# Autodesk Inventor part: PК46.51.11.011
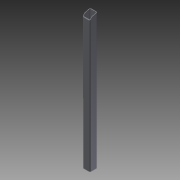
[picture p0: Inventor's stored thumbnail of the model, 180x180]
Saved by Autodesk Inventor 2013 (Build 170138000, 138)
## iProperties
Shininess: 64.0
Length Units: 11269
Angle Units: 11279
Time Units: 11290
Mass Units: 11283
Length Display Precision: 3
Angle Display Precision: 2
Compacted: True
Part Number: PК46.51.11.011
Document SubType Name: Modeling
Created: 2004-07
Material: Steel, Mild
Designer: =<Author>
Manufacturer: Standard
Standards Organization: Custom
Description: pipe
Density: 7.86 g/cm^3
Mass: 903.434 g
Surface Area: 1154.19 cm^2
Volume: 114.941 cm^3
Density: 0.0
Volumn: 0.0
Area: 0.0
PropertySet Name: Model Information
Control State: 0
Master: False
Checked Out: False
Checked Out Date: 2008-10-15
Last Check In Date: 2008-10-15
Author: PVitaliy
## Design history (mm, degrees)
sketch "Эскиз1"
  geometry: L1 (4, 0)-(26, 0); L2 (30, 4)-(30, 26); L3 (26, 30)-(4, 30); L4 (0, 26)-(0, 4); L5 (2, 26)-(2, 4); L6 (4, 2)-(26, 2); L7 (28, 4)-(28, 26); L8 (26, 28)-(4, 28); A1 r 4 centre (4, 26) between (4, 30) and (0, 26); A2 r 4 centre (26, 26) between (30, 26) and (26, 30); A3 r 4 centre (26, 4) between (26, 0) and (30, 4); A4 r 4 centre (4, 4) between (0, 4) and (4, 0); A5 r 2 centre (4, 26) between (4, 28) and (2, 26); A6 r 2 centre (4, 4) between (2, 4) and (4, 2); A7 r 2 centre (26, 4) between (26, 2) and (28, 4); A8 r 2 centre (26, 26) between (28, 26) and (26, 28); 3 further points
  constraints: 16 end point, 16 point on circle, 8 centre point, 8 tangent, 6 point on line, 4 parallel, 2 equal radius, 2 perpendicular, 1 horizontal, 8 other
  dimensions: "d0" = 30 distance of point (0, 30) point (0, 0); "d1" = 30 distance of point (0, 0) point (30, 0); "d2" = 4 radius of A1; "d3" = 4 radius of A2; "d4" = 2 distance between parallel lines of L1 L6
extrude "Выдавливание1" new body sketch "Эскиз1" distance "d5" = 544; taper "d6" = 0 deg
sketch "Эскиз2"
  geometry: L1 (-544, 22)-(-544, 0) reference; L2 (0, 26)-(-544, 26) reference; L3 (0, -4)-(-544, -4) reference; L4 (-544, -4)-(-544, 0) reference; L5 (-544, 22)-(-544, 26) reference; L6 (-544, 26)-(-535.962, -4)
  constraints: 2 end point, 1 point on line
  dimensions: "d7" = 15 deg angle of L6 L1
extrude "Выдавливание2" cut sketch "Эскиз2" stored distance "d8" = 10; taper "d9" = 0 deg
sketch "Эскиз3"
  geometry: L1 (-542.928, 22)-(-537.033, 0) reference; L2 (0, -4)-(-535.962, -4) reference; L3 (-535.962, -4)-(-537.033, 0) reference; L4 (-538.105, 4)-(-527.962, -4)
  constraints: 2 end point, 2 point on line
  dimensions: "d10" = 8 distance of L4.end L2.end; "d11" = 8 distance from line of L4.start L2
extrude "Выдавливание3" cut sketch "Эскиз3" stored distance "d12" = 10; taper "d13" = 0 deg
body "Solid1"
